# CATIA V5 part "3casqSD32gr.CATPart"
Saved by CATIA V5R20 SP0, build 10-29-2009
Part number: 3casqSD32gr
Revision: ANY
Definition: UNKNOWN
Nomenclature: 3casqSD32gr
Source: Unknown
Bounding box of the stored display mesh (mm): x -24.185 to 7.815, y 2.436 to 16.754, z -29.013 to -14.513
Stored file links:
  C:\Users\Utente\Desktop\IO LAVORO\3D X SITO CF\CUMSA\3D files SD\SD 3220\3casqSD32gr.CATPart
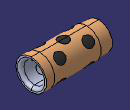
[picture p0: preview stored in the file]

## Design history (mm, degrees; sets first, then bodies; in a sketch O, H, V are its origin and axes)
Body1 "grafito-4-solid2" (main body)
  Solid1: solid without history
Body2 "grafito-2-solid1"
  Solid2: solid without history
Body3 "grafito-2-solid2"
  Solid3: solid without history
Body4 "grafito-5-solid1"
  Solid4: solid without history
Body5 "grafito-5-solid2"
  Solid5: solid without history
Body6 "grafito-3-solid1"
  Solid6: solid without history
Body7 "grafito-3-solid2"
  Solid7: solid without history
Body8 "grafito-1-solid1"
  Solid8: solid without history
Body9 "grafito-4-solid1"
  Solid9: solid without history
Body10 "grafito-1-solid2"
  Solid10: solid without history
Body11 "3CASQSD3220GRF-1-solid1"
  Solid11: solid without history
